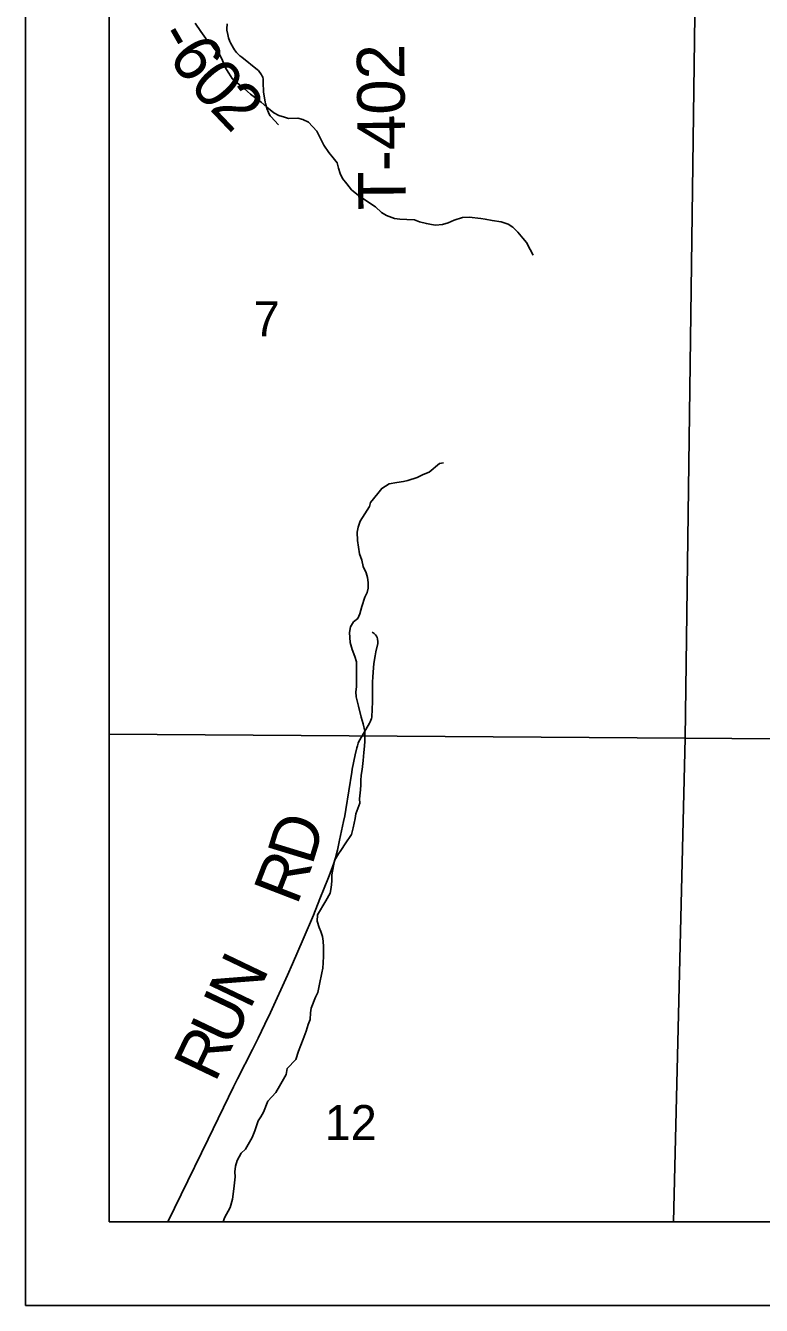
# Model space of a CAD drawing. Extents: x -7.1 to 34, y 0 to 22.
# Drawn here: x 2 to 2.879, y 14 to 15.53 of the extents above; entities that cross this region are included whole.
import ezdxf

# ---------------------------------------------------------------- set-up
doc = ezdxf.new("R2010")
doc.units = 0
for name, color, linetype in [('GM_X_Minor_River', 7, 'Continuous'), ('GM_X_Section', 7, 'Continuous'), ('GM_X_Section_Text', 7, 'Continuous'), ('GM_X_Township_Road', 7, 'Continuous'), ('GM_X_Township_Road_Text', 7, 'Continuous'), ('GM_X_Unincorporated', 7, 'Continuous'), ('SH_Cut_Line', 7, 'Continuous'), ('SH_Data', 7, 'Continuous')]:
    doc.layers.add(name, color=color, linetype=linetype)

msp = doc.modelspace()

# ---------------------------------------------------------------- linework, layer by layer
at = {"layer": 'GM_X_Minor_River'}
for points in [[(2.2028, 15.5332), (2.2094, 15.5231), (2.2152, 15.5148), (2.2217, 15.508), (2.2264, 15.5013), (2.2317, 15.4956), (2.2349, 15.4896), (2.238, 15.4809), (2.2427, 15.4733), (2.2469, 15.4669), (2.2557, 15.4595), (2.2615, 15.4546), (2.2688, 15.4482), (2.2753, 15.4434), (2.2814, 15.4389), (2.2883, 15.4329), (2.2967, 15.4258), (2.3028, 15.4229), (2.3093, 15.4207), (2.3143, 15.4193), (2.3252, 15.4194), (2.3313, 15.418), (2.3382, 15.4147), (2.3482, 15.4042), (2.3564, 15.3872), (2.3622, 15.3785), (2.3676, 15.3721), (2.3722, 15.3661), (2.3738, 15.3597), (2.3758, 15.3536), (2.3789, 15.3475), (2.3839, 15.3412), (2.3893, 15.334), (2.3958, 15.3288), (2.4066, 15.321), (2.418, 15.3135), (2.4253, 15.3068), (2.4311, 15.3031), (2.441, 15.2998), (2.4474, 15.2987), (2.4554, 15.2985), (2.4648, 15.2979), (2.4709, 15.2957), (2.4789, 15.2935), (2.485, 15.2925), (2.4899, 15.2918), (2.4982, 15.2923), (2.505, 15.2943), (2.5122, 15.2975), (2.5223, 15.3007), (2.5299, 15.3012), (2.5439, 15.2998), (2.5493, 15.2988), (2.5576, 15.2974), (2.5682, 15.2957), (2.5766, 15.2927), (2.5823, 15.2894), (2.5881, 15.2834), (2.5943, 15.2763), (2.5985, 15.271), (2.6028, 15.2627), (2.6066, 15.2557)], [(2.3492, 14.3742), (2.3513, 14.3842), (2.3542, 14.3975), (2.3552, 14.4033), (2.3555, 14.4097), (2.3562, 14.4177), (2.356, 14.4288), (2.3555, 14.4356), (2.3547, 14.4413), (2.3527, 14.447), (2.3507, 14.4519), (2.3484, 14.4595), (2.349, 14.4671), (2.3586, 14.4836), (2.3638, 14.4928), (2.3652, 14.4997), (2.3658, 14.5073), (2.3661, 14.5149), (2.3671, 14.5214), (2.3693, 14.5321), (2.3741, 14.5398), (2.3774, 14.5452), (2.3818, 14.5521), (2.3896, 14.5629), (2.3914, 14.5709), (2.3939, 14.582), (2.3946, 14.5877), (2.3993, 14.6007), (2.3992, 14.6057), (2.4002, 14.6163), (2.4005, 14.6224), (2.4008, 14.6278), (2.4011, 14.6342), (2.4021, 14.6407), (2.4035, 14.6514), (2.4041, 14.6613), (2.4051, 14.6686), (2.4054, 14.6746), (2.4052, 14.6868), (2.4036, 14.6955), (2.4012, 14.7035), (2.398, 14.7164), (2.3952, 14.7278), (2.3947, 14.7335), (2.3954, 14.7396), (2.3956, 14.7502), (2.3955, 14.7586), (2.3953, 14.7696), (2.3933, 14.7761), (2.3902, 14.7844), (2.3878, 14.7927), (2.3869, 14.8045), (2.3883, 14.8114), (2.392, 14.8172), (2.3972, 14.8214), (2.3994, 14.8268), (2.4019, 14.8356), (2.4055, 14.8467), (2.4081, 14.8524), (2.4095, 14.8578), (2.4095, 14.8643), (2.4086, 14.8703), (2.407, 14.876), (2.4035, 14.8836), (2.4019, 14.8912), (2.3991, 14.8987), (2.3966, 14.9147), (2.3961, 14.9246), (2.3975, 14.9307), (2.4, 14.9379), (2.4108, 14.9552), (2.4122, 14.9602), (2.4208, 14.971), (2.4256, 14.9768), (2.4346, 14.9822), (2.4437, 14.9839), (2.4516, 14.9852), (2.4569, 14.9864), (2.4678, 14.99), (2.4753, 14.9935), (2.4821, 14.9963), (2.4945, 15.0068), (2.4994, 15.0076)], [(2.2359, 14.1), (2.2377, 14.1046), (2.2443, 14.1172), (2.2472, 14.1272), (2.2489, 14.1394), (2.2506, 14.1539), (2.2501, 14.1599), (2.2508, 14.1664), (2.253, 14.1733), (2.2578, 14.1821), (2.2626, 14.1868), (2.2707, 14.2006), (2.274, 14.2087), (2.278, 14.2205), (2.281, 14.2255), (2.2843, 14.2309), (2.2894, 14.2443), (2.2991, 14.2547), (2.3035, 14.262), (2.3113, 14.2762), (2.3127, 14.2831), (2.3228, 14.2939), (2.326, 14.3038), (2.3319, 14.3184), (2.3351, 14.328), (2.3377, 14.336), (2.3399, 14.3417), (2.3405, 14.3497), (2.3412, 14.3555), (2.3463, 14.3685), (2.3492, 14.3742)]]:
    msp.add_lwpolyline(points, dxfattribs=at)
at = {"layer": 'GM_X_Section'}
msp.add_lwpolyline([(2.8016, 15.6921), (3.8055, 15.6719), (3.7918, 14.7389), (3.7909, 14.6711), (2.7883, 14.6781)], close=True, dxfattribs=at)
at = {"layer": 'GM_X_Township_Road'}
for points in [[(2.1, 17.7253), (2.1, 14.1), (6.633, 14.1), (6.6565, 15.1357), (6.6586, 15.2372), (6.6748, 15.9993), (6.6822, 16.3488), (6.7058, 17.2839), (6.7118, 17.7486)], [(2.3022, 15.4116), (2.2929, 15.4217), (2.2921, 15.4225), (2.2912, 15.4243), (2.2893, 15.4285), (2.2886, 15.4301), (2.2866, 15.437), (2.2862, 15.4388), (2.2846, 15.4487), (2.2844, 15.4505), (2.284, 15.4626), (2.2838, 15.4664), (2.2834, 15.4688), (2.2829, 15.47), (2.2821, 15.4714), (2.2782, 15.4764), (2.2773, 15.4773), (2.2583, 15.4924), (2.2562, 15.494), (2.2529, 15.4972), (2.2521, 15.498), (2.2496, 15.5013), (2.2484, 15.5032), (2.2448, 15.5096), (2.2441, 15.5113), (2.2425, 15.5158), (2.2416, 15.5196), (2.2406, 15.5248), (2.2404, 15.5266), (2.2407, 15.5323)], [(2.1698, 14.1), (2.1859, 14.1326), (2.218, 14.1987), (2.2485, 14.2612), (2.2534, 14.2709), (2.2712, 14.306), (2.2779, 14.3197), (2.2858, 14.3363), (2.2925, 14.3504), (2.313, 14.3949), (2.319, 14.4083), (2.3318, 14.4381), (2.3439, 14.4667), (2.3518, 14.486), (2.362, 14.5118), (2.3664, 14.5234), (2.3687, 14.53), (2.3702, 14.5352), (2.3726, 14.5444), (2.3753, 14.5561), (2.3801, 14.5787), (2.3814, 14.5853), (2.3827, 14.5931), (2.3897, 14.6375), (2.3904, 14.6413), (2.3939, 14.6583), (2.3957, 14.6665), (2.3965, 14.6692), (2.3975, 14.6723), (2.3987, 14.675), (2.3993, 14.6763), (2.4109, 14.6963), (2.4116, 14.6977), (2.4132, 14.7016), (2.4137, 14.7034), (2.4139, 14.7052), (2.4142, 14.7111), (2.4144, 14.7236), (2.4145, 14.7454), (2.4148, 14.7515), (2.4156, 14.7625), (2.4162, 14.7677), (2.4176, 14.7766), (2.4186, 14.7814), (2.4208, 14.7916), (2.421, 14.7934), (2.4207, 14.7969), (2.4202, 14.7985), (2.4192, 14.8002), (2.418, 14.8018), (2.4164, 14.8035), (2.4143, 14.8051)]]:
    msp.add_lwpolyline(points, dxfattribs=at)
at = {"layer": 'GM_X_Unincorporated'}
for points in [[(2.1, 15.7044), (2.1, 14.6831), (2.7883, 14.6781), (2.8016, 15.6921)], [(2.1, 14.6831), (2.1, 14.1), (2.7742, 14.1), (2.7883, 14.6781)], [(2.7742, 14.1), (3.7847, 14.1), (3.7909, 14.6711), (2.7883, 14.6781)]]:
    msp.add_lwpolyline(points, close=True, dxfattribs=at)
at = {"layer": 'SH_Cut_Line'}
msp.add_lwpolyline([(2.1, 17.7253), (2.1, 14.1), (8.9, 14.1), (8.9, 17.7079), (8.6668, 17.7136), (8.4472, 17.7189), (7.7202, 17.7285), (6.7118, 17.7486), (6.3575, 17.7557), (6.1904, 17.7592), (5.7514, 17.7685), (5.5047, 17.7737), (5.1115, 17.7819), (5.0544, 17.7831), (5.0443, 17.7832), (4.7094, 17.7848), (4.5657, 17.7857), (4.3, 17.7873), (3.8304, 17.7952), (3.8238, 17.6717), (3.7215, 17.6707), (3.0659, 17.6986), (2.7886, 17.7105), (2.5551, 17.7155)], close=True, dxfattribs=at)
at = {"layer": 'SH_Data'}
for p, q in [((2, 21), (2, 14)), ((2.1, 20.9), (2.1, 14.1)), ((2.1, 14.1), (8.9, 14.1)), ((2.1, 14.1), (2.1, 14.1)), ((2, 14), (9, 14))]:
    msp.add_line(p, q, dxfattribs=at)

# ---------------------------------------------------------------- texts
at = {"layer": 'GM_X_Section_Text'}
for s, height, p in [('7', 0.0419, (2.2724, 15.1587)), ('12', 0.04186, (2.3574, 14.1977))]:
    msp.add_text(s, height=height, rotation=0, dxfattribs=at).set_placement(p)
at = {"layer": 'GM_X_Township_Road_Text'}
for s, height, rotation, p in [('-', 0.0568, 299.7705, (2.1553, 15.5178)), ('6', 0.0568, 304.4085, (2.1695, 15.4933)), ('T-402', 0.05682, 90.5614, (2.4544, 15.31)), ('0', 0.0568, 311.8339, (2.1942, 15.4581)), ('2', 0.0568, 313.5001, (2.2188, 15.4307)), ('D', 0.0568, 73.0228, (2.3424, 14.525)), ('R', 0.0568, 68.8871, (2.3242, 14.4773)), ('N', 0.0568, 64.3734, (2.268, 14.3525)), ('U', 0.0568, 64.5363, (2.2465, 14.3074)), ('R', 0.0568, 64.5382, (2.2264, 14.2653))]:
    msp.add_text(s, height=height, rotation=rotation, dxfattribs=at).set_placement(p)

doc.saveas('drawing.dxf')
